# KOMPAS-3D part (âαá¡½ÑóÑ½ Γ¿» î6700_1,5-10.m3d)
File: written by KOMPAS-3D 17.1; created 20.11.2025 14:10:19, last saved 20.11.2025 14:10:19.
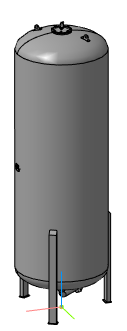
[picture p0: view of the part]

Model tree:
1. Операция без истории:1

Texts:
  REVIT MATERIAL OVERRIDDEN
  REVIT MATERIAL ID
  REVIT SUBCATEGORY ID
  REVIT CATEGORY ID
  REVIT ELEMENT ID
  REVIT BREP TAG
